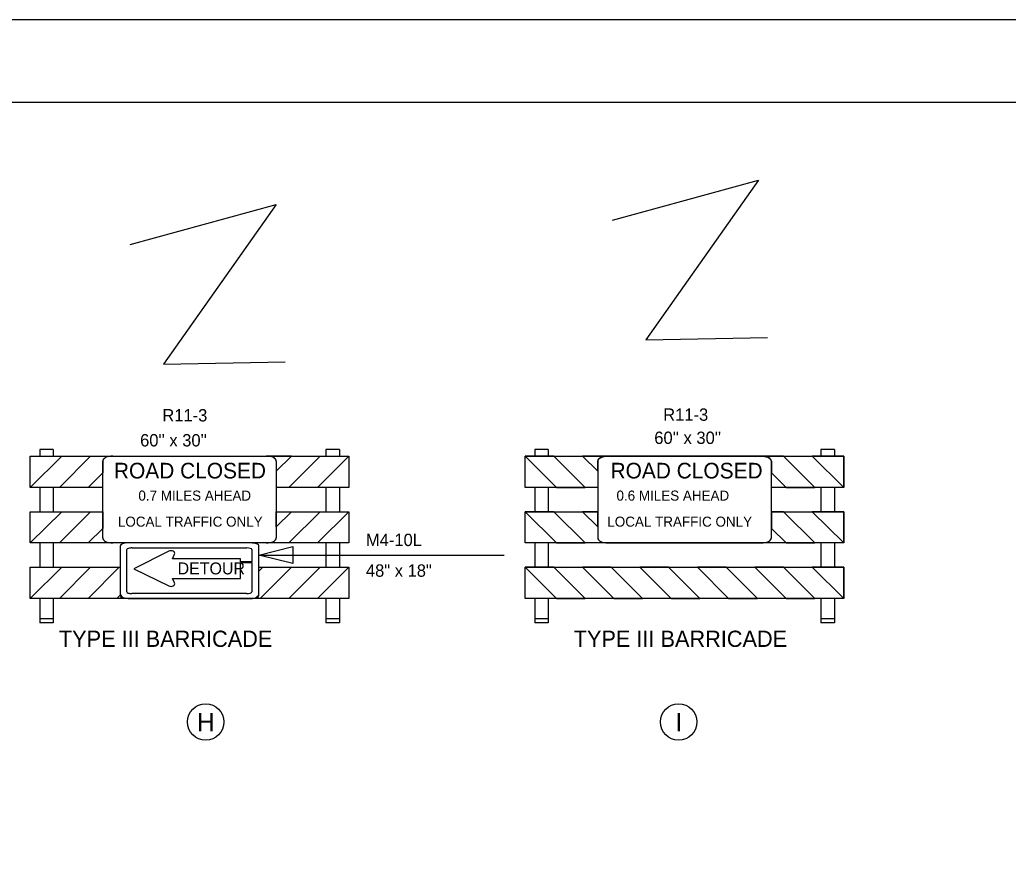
# Model space of a CAD drawing. Extents: x 2157572 to 5059327, y 715220 to 1674494.
# Drawn here: x 2161279 to 2163670, y 729076 to 731089 of the extents above; entities that cross this region are included whole.
import ezdxf

# ---------------------------------------------------------------- set-up
doc = ezdxf.new("R2010")
doc.units = 0
for name, color, linetype in [('Exist Cultural Church Label', 7, 'Continuous'), ('Exist Hydrographic Creek Double Shore Label', 7, 'Continuous'), ('Exist Road Secondary Structure Culvert Number Label', 7, 'Continuous'), ('Exist Road Secondary Type 51 Divided Label', 7, 'Continuous'), ('Level 54', 7, 'Continuous'), ('Map Preparation Border Control Points', 7, 'Continuous'), ('Map Preparation County Base Legend Highway Garage or Maintenance Office', 7, 'Continuous'), ('Map Preparation County Base Legend Lighthouse', 7, 'Continuous'), ('Map Preparation County Inset Control Points', 7, 'Continuous'), ('Map Preparation County North Arrow White Shapes', 7, 'Continuous')]:
    doc.layers.add(name, color=color, linetype=linetype)

msp = doc.modelspace()

# ---------------------------------------------------------------- linework, layer by layer
at = {"layer": 'Exist Cultural Church Label'}
for centre in [(2161728.7, 729390.6), (2162872.4, 729390.6)]:
    msp.add_circle(centre, 44.1, dxfattribs=at)
at = {"layer": 'Exist Hydrographic Creek Double Shore Label'}
for p, q in [((2162792.8, 730315), (2163087.2, 730320.4)), ((2161626.1, 730256.1), (2161920.5, 730261.4))]:
    msp.add_line(p, q, dxfattribs=at)
for points in [[(2162712.6, 730604.2), (2163065.8, 730700.6), (2162792.8, 730315)], [(2161545.9, 730545.3), (2161899.1, 730641.7), (2161626.1, 730256.1)]]:
    msp.add_lwpolyline(points, dxfattribs=at)
at = {"layer": 'Exist Road Secondary Type 51 Divided Label'}
msp.add_lwpolyline([(2157571.9, 722288.7), (2171075.9, 722288.7), (2171075.9, 731088.6), (2157571.9, 731088.6)], close=True, dxfattribs=at)
at = {"layer": 'Level 54'}
for p, q in [((2161359.7, 730049.9), (2161327, 730049.9)), ((2161327, 730049.9), (2161327, 730033.5)), ((2161359.7, 730049.9), (2161359.7, 730033.5)), ((2162051.8, 730049.9), (2162019.1, 730049.9)), ((2162019.1, 730049.9), (2162019.1, 730033.5)), ((2162051.8, 730049.9), (2162051.8, 730033.5)), ((2161304.1, 730033.5), (2162074.7, 730033.5)), ((2161304.1, 729958), (2161304.1, 730033.5)), ((2161304.1, 729958), (2161304.1, 730033.5)), ((2161304.1, 730033.5), (2161380.9, 730033.5)), ((2161380.9, 730033.5), (2161304.1, 729958)), ((2161374.7, 729958), (2161450.3, 730033.5)), ((2161450.3, 730033.5), (2161503.9, 730033.5)), ((2161479.4, 730021.3), (2161479.4, 729993.3)), ((2161936, 730033.5), (2161875, 730033.5)), ((2161899.4, 729996.9), (2161936, 730033.5)), ((2161899.4, 730021.3), (2161899.4, 729996.9)), ((2161899.4, 730021.3), (2161899.4, 730021.3)), ((2161929.8, 729958), (2162005.3, 730033.5)), ((2162074.7, 730033.5), (2161999.1, 729958)), ((2162005.3, 730033.5), (2162074.7, 730033.5)), ((2162074.7, 730033.5), (2162074.7, 729958)), ((2161479.4, 729993.3), (2161444.1, 729958)), ((2161479.4, 729958), (2161304.1, 729958)), ((2161327, 729958), (2161327, 729899.1)), ((2161359.7, 729958), (2161359.7, 729899.1)), ((2161444.1, 729958), (2161374.7, 729958)), ((2162074.7, 729958), (2161899.4, 729958)), ((2161999.1, 729958), (2161929.8, 729958)), ((2162019.1, 729958), (2162019.1, 729899.1)), ((2162051.8, 729958), (2162051.8, 729899.1)), ((2161304.1, 729823.5), (2161304.1, 729899.1)), ((2161304.1, 729823.5), (2161304.1, 729899.1)), ((2161304.1, 729899.1), (2161380.9, 729899.1)), ((2161380.9, 729899.1), (2161304.1, 729823.5)), ((2161304.1, 729899.1), (2161479.4, 729899.1)), ((2161374.7, 729823.5), (2161450.3, 729899.1)), ((2161450.3, 729899.1), (2161479.4, 729899.1)), ((2161899.4, 729899.1), (2162074.7, 729899.1)), ((2161899.4, 729862.4), (2161899.4, 729899.1)), ((2161899.4, 729899.1), (2161936, 729899.1)), ((2161936, 729899.1), (2161899.4, 729862.4)), ((2161929.8, 729823.5), (2162005.3, 729899.1)), ((2162074.7, 729899.1), (2161999.1, 729823.5)), ((2162005.3, 729899.1), (2162074.7, 729899.1)), ((2162074.7, 729899.1), (2162074.7, 729823.5)), ((2162074.7, 729823.5), (2161304.1, 729823.5)), ((2161327, 729823.5), (2161327, 729764.6)), ((2161359.7, 729823.5), (2161359.7, 729764.6)), ((2161444.1, 729823.5), (2161374.7, 729823.5)), ((2161999.1, 729823.5), (2161929.8, 729823.5)), ((2162019.1, 729823.5), (2162019.1, 729764.6)), ((2162051.8, 729823.5), (2162051.8, 729764.6)), ((2161537.8, 729705.4), (2161537.8, 729807.3)), ((2161550.2, 729811.4), (2161827.7, 729811.7)), ((2161639.5, 729803.8), (2161554.5, 729761.2)), ((2161648.3, 729785.5), (2161653.2, 729796.4)), ((2161840.5, 729807.3), (2161840.5, 729777.5)), ((2161812.6, 729785.5), (2161648.3, 729785.5)), ((2161812.6, 729777.5), (2161812.6, 729785.5)), ((2161840.5, 729777.5), (2161812.6, 729777.5)), ((2161812.6, 729737.6), (2161812.6, 729776.6)), ((2161812.6, 729776.6), (2161840.5, 729776.6)), ((2161840.5, 729776.6), (2161840.2, 729705.4)), ((2161857.4, 729794.1), (2162450.7, 729794.1)), ((2161304.1, 729689.1), (2161304.1, 729764.6)), ((2161304.1, 729764.6), (2161380.9, 729764.6)), ((2161380.9, 729764.6), (2161304.1, 729689.1)), ((2161304.1, 729689.1), (2161304.1, 729764.6)), ((2161304.1, 729764.6), (2161521.4, 729764.6)), ((2161374.7, 729689.1), (2161450.3, 729764.6)), ((2161519.6, 729764.6), (2161444.1, 729689.1)), ((2161450.3, 729764.6), (2161519.6, 729764.6)), ((2161554.5, 729761.2), (2161639.5, 729719.6)), ((2161857.4, 729755.4), (2161866.6, 729764.6)), ((2161857.4, 729764.6), (2162074.7, 729764.6)), ((2161857.4, 729701.3), (2161857.4, 729755.4)), ((2161936, 729764.6), (2161860.4, 729689.1)), ((2161866.6, 729764.6), (2161936, 729764.6)), ((2161929.8, 729689.1), (2162005.3, 729764.6)), ((2162074.7, 729764.6), (2161999.1, 729689.1)), ((2162005.3, 729764.6), (2162074.7, 729764.6)), ((2162074.7, 729764.6), (2162074.7, 729689.1)), ((2161653.2, 729727), (2161648.4, 729737.6)), ((2161648.4, 729737.6), (2161812.6, 729737.6)), ((2161827.4, 729701.2), (2161550.2, 729701.2)), ((2162074.7, 729689.1), (2161304.1, 729689.1)), ((2161327, 729689.1), (2161327, 729630.2)), ((2161359.7, 729689.1), (2161359.7, 729630.2)), ((2161444.1, 729689.1), (2161374.7, 729689.1)), ((2161513.4, 729689.1), (2161522.2, 729697.9)), ((2161541, 729689.1), (2161513.4, 729689.1)), ((2161541, 729689.1), (2161837.8, 729689.1)), ((2161860.4, 729689.1), (2161837.9, 729689.1)), ((2161999.1, 729689.1), (2161929.8, 729689.1)), ((2162019.1, 729689.1), (2162019.1, 729630.2)), ((2162051.8, 729689.1), (2162051.8, 729630.2)), ((2161359.7, 729640), (2161327, 729640)), ((2161359.7, 729630.2), (2161327, 729630.2)), ((2162051.8, 729640), (2162019.1, 729640)), ((2162051.8, 729630.2), (2162019.1, 729630.2))]:
    msp.add_line(p, q, dxfattribs=at)
for points in [[(2161479.4, 729835.8), (2161479.4, 730021.3)], [(2161503.9, 730033.5), (2161874.9, 730033.5)], [(2161899.4, 730021.3), (2161899.4, 729835.8)], [(2161479.4, 729899.1), (2161479.4, 729858.8), (2161444.1, 729823.5)], [(2161874.9, 729823.5), (2161503.9, 729823.5)], [(2161837.8, 729823.5), (2161541, 729823.5)], [(2161521.4, 729816.2), (2161521.4, 729696.4)], [(2161857.4, 729696.4), (2161857.4, 729816.2)]]:
    msp.add_lwpolyline(points, dxfattribs=at)
msp.add_lwpolyline([(2161939.1, 729773.7), (2161857.4, 729794.1), (2161939.1, 729814.6)], close=True, dxfattribs=at)
msp.add_lwpolyline([(2161939.1, 729773.7), (2161857.4, 729794.1), (2161939.1, 729814.6)], close=True, dxfattribs=at)
for centre, major_axis, ratio, start_param, end_param in [((2161503.9, 730021.3), (-24.5, 0), 0.5, 4.712162, 6.283185), ((2161503.9, 730021.3), (-24.5, 0), 0.5, 4.712162, 6.283185), ((2161874.9, 730021.3), (24.5, 0), 0.5, 0, 1.570881), ((2161874.9, 730021.3), (24.5, 0), 0.5, 0, 1.570796), ((2161503.9, 729835.8), (-24.5, 0), 0.5, 0, 1.570796), ((2161541, 729816.2), (-19.6, 0), 0.375009, 4.712389, 6.283185), ((2161837.8, 729816.2), (19.6, 0), 0.375009, 0, 1.571024), ((2161874.9, 729835.8), (-24.5, 0), 0.5, 1.570796, 3.141593), ((2161550.4, 729807.3), (-12.6, 0), 0.337508, 4.712198, 6.283193), ((2161644.7, 729798.1), (-9, 0), 0.720018, 2.830616, 5.313575), ((2161827.6, 729807.3), (12.6, 0), 0.337508, 6.283183, 7.85379), ((2161644.7, 729724.9), (-9, 0), 0.720018, 0.969609, 3.452568), ((2161550.2, 729705.4), (-12.6, 0), 0.337508, 0.000008, 1.570982), ((2161827.4, 729705.4), (12.6, 0), 0.337508, 4.712575, 6.283183), ((2161837.8, 729701.3), (-19.6, 0), 0.625, 1.570796, 3.141593), ((2161541, 729696.4), (19.6, 0), 0.375009, 3.141593, 4.712389), ((2161541, 729701.3), (-19.6, 0), 0.625, 0.287132, 1.570688), ((2161837.8, 729696.4), (19.6, 0), 0.375009, 4.712389, 6.283185)]:
    msp.add_ellipse(centre, major_axis=major_axis, ratio=ratio, start_param=start_param, end_param=end_param, dxfattribs=at)
at = {"layer": 'Map Preparation Border Control Points'}
for points in [[(2162676.9, 730021.3), (2162676.9, 729835.8)], [(2163072.4, 730033.5), (2162701.4, 730033.5)], [(2163096.9, 729835.8), (2163096.9, 730021.3)], [(2162701.4, 729823.5), (2163072.4, 729823.5)], [(2162738.5, 729823.5), (2163035.3, 729823.5)]]:
    msp.add_lwpolyline(points, dxfattribs=at)
for centre, major_axis, start_param, end_param in [((2162701.4, 730021.3), (-24.5, 0), 4.712304, 6.283185), ((2163072.4, 730021.3), (24.5, 0), 0, 1.571024), ((2162701.4, 729835.8), (24.5, 0), 3.141593, 4.712389), ((2163072.4, 729835.8), (24.5, 0), 4.712389, 6.283185)]:
    msp.add_ellipse(centre, major_axis=major_axis, ratio=0.5, start_param=start_param, end_param=end_param, dxfattribs=at)
at = {"layer": 'Map Preparation County Base Legend Highway Garage or Maintenance Office'}
for centre in [(2161728.7, 729390.6), (2162872.4, 729390.6)]:
    msp.add_circle(centre, 44.1, dxfattribs=at)
at = {"layer": 'Map Preparation County Base Legend Lighthouse'}
for p, q in [((2162557.2, 730049.9), (2162524.5, 730049.9)), ((2162524.5, 730049.9), (2162524.5, 730033.5)), ((2162557.2, 730049.9), (2162557.2, 730033.5)), ((2163249.3, 730049.9), (2163216.6, 730049.9)), ((2163216.6, 730049.9), (2163216.6, 730033.5)), ((2163249.3, 730049.9), (2163249.3, 730033.5)), ((2162501.6, 730033.5), (2163272.2, 730033.5)), ((2162501.6, 729958), (2162501.6, 730033.5)), ((2162570.9, 730033.5), (2162501.6, 730033.5)), ((2162501.6, 730033.5), (2162577.2, 729958)), ((2162646.5, 729958), (2162570.9, 730033.5)), ((2162709.6, 730033.5), (2162640.3, 730033.5)), ((2162640.3, 730033.5), (2162676.9, 729996.9)), ((2162701.2, 730033.5), (2162709.6, 730033.5)), ((2163126, 730033.5), (2163056.7, 730033.5)), ((2163201.6, 729958), (2163126, 730033.5)), ((2163272.2, 730033.5), (2163195.3, 730033.5)), ((2163195.3, 730033.5), (2163272.2, 729958)), ((2163272.2, 730033.5), (2163272.2, 729958)), ((2163272.2, 729958), (2163272.2, 730033.5)), ((2162676.9, 729958), (2162501.6, 729958)), ((2162524.5, 729958), (2162524.5, 729899.1)), ((2162557.2, 729958), (2162557.2, 729899.1)), ((2162577.2, 729958), (2162646.5, 729958)), ((2163272.2, 729958), (2163096.9, 729958)), ((2163132.2, 729958), (2163201.6, 729958)), ((2163216.6, 729958), (2163216.6, 729899.1)), ((2163249.3, 729958), (2163249.3, 729899.1)), ((2162501.6, 729823.5), (2162501.6, 729899.1)), ((2162570.9, 729899.1), (2162501.6, 729899.1)), ((2162501.6, 729899.1), (2162577.2, 729823.5)), ((2162501.6, 729899.1), (2162676.9, 729899.1)), ((2162646.5, 729823.5), (2162570.9, 729899.1)), ((2162676.9, 729899.1), (2162640.3, 729899.1)), ((2162640.3, 729899.1), (2162676.9, 729862.4)), ((2162676.9, 729881.3), (2162676.9, 729899.1)), ((2163096.9, 729899.1), (2163272.2, 729899.1)), ((2163201.6, 729823.5), (2163126, 729899.1)), ((2163272.2, 729899.1), (2163195.3, 729899.1)), ((2163195.3, 729899.1), (2163272.2, 729823.5)), ((2163272.2, 729899.1), (2163272.2, 729823.5)), ((2163272.2, 729823.5), (2163272.2, 729899.1)), ((2162676.9, 729862.4), (2162676.9, 729881.3)), ((2163096.9, 729858.8), (2163132.2, 729823.5)), ((2163272.2, 729823.5), (2162501.6, 729823.5)), ((2162524.5, 729823.5), (2162524.5, 729764.6)), ((2162557.2, 729823.5), (2162557.2, 729764.6)), ((2162577.2, 729823.5), (2162646.5, 729823.5)), ((2163132.2, 729823.5), (2163201.6, 729823.5)), ((2163216.6, 729823.5), (2163216.6, 729764.6)), ((2163249.3, 729823.5), (2163249.3, 729764.6)), ((2162570.9, 729764.6), (2162501.6, 729764.6)), ((2162501.6, 729764.6), (2162577.2, 729689.1)), ((2162501.6, 729764.6), (2163272.2, 729764.6)), ((2162501.6, 729689.1), (2162501.6, 729764.6)), ((2162646.5, 729689.1), (2162570.9, 729764.6)), ((2162709.6, 729764.6), (2162640.3, 729764.6)), ((2162640.3, 729764.6), (2162715.8, 729689.1)), ((2162785.2, 729689.1), (2162709.6, 729764.6)), ((2162848.3, 729764.6), (2162779, 729764.6)), ((2162779, 729764.6), (2162854.5, 729689.1)), ((2162923.9, 729689.1), (2162848.3, 729764.6)), ((2162987.3, 729764.6), (2162918, 729764.6)), ((2162918, 729764.6), (2162993.5, 729689.1)), ((2163062.9, 729689.1), (2162987.3, 729764.6)), ((2163126, 729764.6), (2163056.7, 729764.6)), ((2163056.7, 729764.6), (2163132.2, 729689.1)), ((2163201.6, 729689.1), (2163126, 729764.6)), ((2163272.2, 729764.6), (2163195.3, 729764.6)), ((2163195.3, 729764.6), (2163272.2, 729689.1)), ((2163272.2, 729689.1), (2163272.2, 729764.6)), ((2163272.2, 729764.6), (2163272.2, 729689.1)), ((2163272.2, 729689.1), (2162501.6, 729689.1)), ((2162524.5, 729689.1), (2162524.5, 729630.2)), ((2162557.2, 729689.1), (2162557.2, 729630.2)), ((2162577.2, 729689.1), (2162646.5, 729689.1)), ((2162715.8, 729689.1), (2162785.2, 729689.1)), ((2162854.5, 729689.1), (2162923.9, 729689.1)), ((2162993.5, 729689.1), (2163062.9, 729689.1)), ((2163132.2, 729689.1), (2163201.6, 729689.1)), ((2163216.6, 729689.1), (2163216.6, 729630.2)), ((2163249.3, 729689.1), (2163249.3, 729630.2)), ((2162557.2, 729640), (2162524.5, 729640)), ((2162557.2, 729630.2), (2162524.5, 729630.2)), ((2163249.3, 729640), (2163216.6, 729640)), ((2163249.3, 729630.2), (2163216.6, 729630.2))]:
    msp.add_line(p, q, dxfattribs=at)
for points in [[(2162676.9, 729996.9), (2162676.9, 730021.5), (2162677.9, 730024.7), (2162680.5, 730027.6), (2162684.1, 730029.9), (2162690.2, 730032.1), (2162696, 730033.2), (2162701.2, 730033.5)], [(2163056.7, 730033.5), (2163075.7, 730033.4), (2163080.3, 730032.9), (2163084.5, 730031.9), (2163087.6, 730030.9), (2163090.5, 730029.5), (2163092.9, 730028), (2163094.8, 730026.2), (2163095.9, 730024.8), (2163096.9, 730021.3), (2163096.9, 729993.3), (2163132.2, 729958)], [(2163126, 729899.1), (2163096.9, 729899.1), (2163096.9, 729858.8)]]:
    msp.add_lwpolyline(points, dxfattribs=at)
at = {"layer": 'Map Preparation County Inset Control Points'}
msp.add_lwpolyline([(2162738.5, 730033.5), (2163035.3, 730033.5)], dxfattribs=at)
at = {"layer": 'Map Preparation County North Arrow White Shapes'}
msp.add_lwpolyline([(2170875.9, 730888.7), (2158875.9, 730888.7), (2158875.9, 722488.7), (2170875.9, 722488.7)], close=True, dxfattribs=at)

# ---------------------------------------------------------------- texts
at = {"layer": 'Exist Cultural Church Label'}
for s, p in [('H', (2161707.6, 729368.4)), ('I', (2162864.7, 729368.1))]:
    msp.add_text(s, height=44.3, dxfattribs=at).set_placement(p)
at = {"layer": 'Exist Road Secondary Structure Culvert Number Label'}
for s, p in [('R11-3', (2162835.2, 730118.9)), ("60'' x 30''", (2162813.6, 730062.9))]:
    msp.add_text(s, height=29.88, dxfattribs=at).set_placement(p)
at = {"layer": 'Level 54'}
for s, height, p in [('R11-3', 29.88, (2161623.7, 730117.3)), ("60'' x 30''", 29.88, (2161569.9, 730056.9)), ('ROAD CLOSED', 37.785, (2161506.6, 729979.5)), ('ROAD CLOSED', 37.785, (2162707.8, 729979.5)), ('0.7 MILES AHEAD', 24.287, (2161565.8, 729925.9)), ('0.6 MILES AHEAD', 24.287, (2162722.2, 729925.9)), ('LOCAL TRAFFIC ONLY', 24.287, (2161516.2, 729862.9)), ('LOCAL TRAFFIC ONLY', 24.287, (2162700, 729862.9)), ('M4-10L', 29.88, (2162116.1, 729816)), ('DETOUR', 28.88, (2161660.6, 729747.5)), ('48" x 18"', 29.88, (2162116.1, 729741.8)), ('TYPE III BARRICADE', 39.25, (2161373.5, 729572.2))]:
    msp.add_text(s, height=height, dxfattribs=at).set_placement(p)
at = {"layer": 'Map Preparation County Base Legend Lighthouse'}
msp.add_text('TYPE III BARRICADE', height=39.25, dxfattribs=at).set_placement((2162618.7, 729572.2))

doc.saveas('drawing.dxf')
